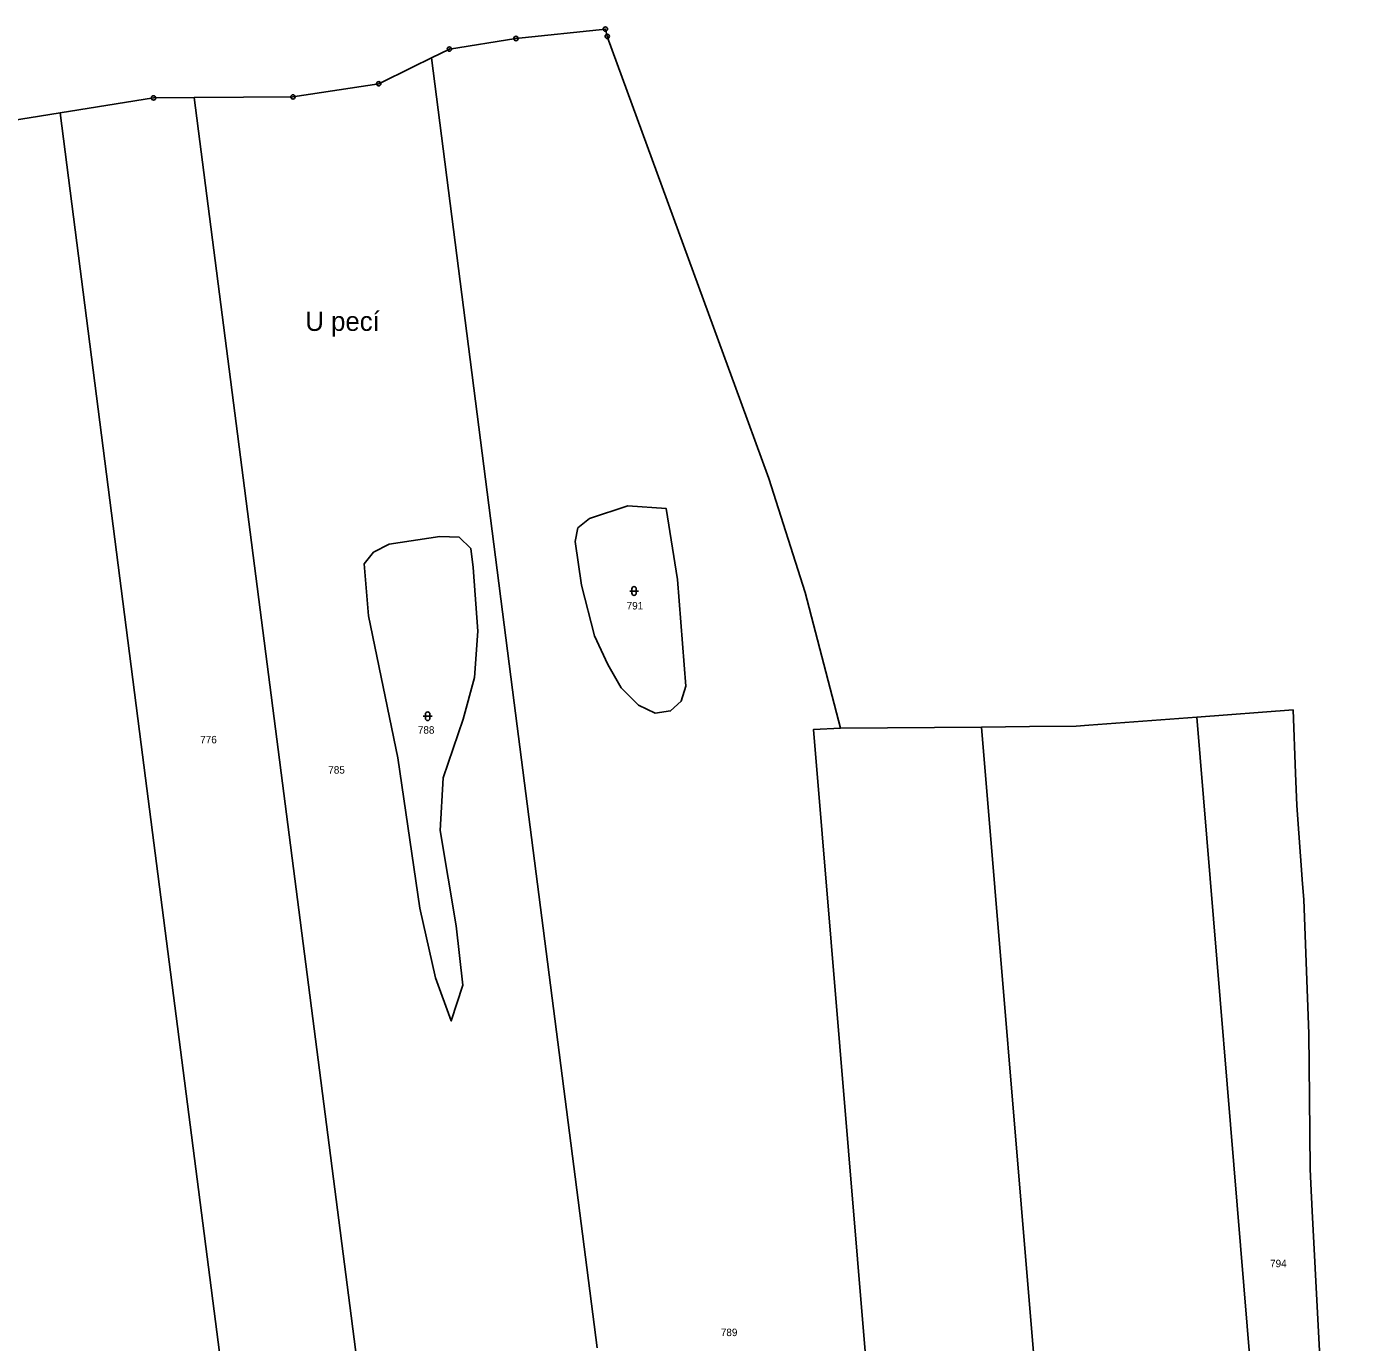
# Model space of a CAD drawing. Extents: x -754445 to -751443, y -1030748 to -1028224.
# Drawn here: x -751875.1 to -751567.6, y -1028889.3 to -1028588.8 of the extents above; entities that cross this region are included whole.
import ezdxf
from ezdxf.enums import TextEntityAlignment as Align

# ---------------------------------------------------------------- set-up
doc = ezdxf.new("R2010")
doc.units = 0
doc.header["$LTSCALE"] = 0.68
for name, color, linetype, lineweight in [('1', 7, 'Continuous', 25), ('3', 7, 'Continuous', 25), ('7', 7, 'Continuous', 13), ('8', 7, 'Continuous', 25)]:
    doc.layers.add(name, color=color, linetype=linetype, lineweight=lineweight)
doc.layers.add('2', color=7, linetype='Continuous')

msp = doc.modelspace()

# ---------------------------------------------------------------- linework, layer by layer
at = {"layer": '1'}
for p, q in [((-751657.05, -1028748.75), (-751689.28, -1028749)), ((-751580.13, -1028885.51), (-751581.5, -1028859.37))]:
    msp.add_line(p, q, dxfattribs=at)
for points in [[(-751742.99, -1028589.3), (-751763.44, -1028591.45), (-751778.63, -1028593.86), (-751782.74, -1028595.88)], [(-751713.49, -1028670.53), (-751714.87, -1028666.76), (-751742.56, -1028590.96), (-751742.99, -1028589.3)], [(-751782.74, -1028595.88), (-751787.07, -1028598), (-751794.77, -1028601.78)], [(-751744.86, -1028890.61), (-751763.8, -1028743.25), (-751782.74, -1028595.88)], [(-751794.77, -1028601.78), (-751814.38, -1028604.79), (-751836.91, -1028604.96)], [(-751836.91, -1028604.96), (-751846.22, -1028605.03), (-751867.56, -1028608.43)], [(-751799.79, -1028893.34), (-751818.35, -1028749.15), (-751836.91, -1028604.96)], [(-751867.56, -1028608.43), (-751881.26, -1028610.61), (-751910.89, -1028616.28), (-751944.04, -1028629.9), (-751979.64, -1028641.44)], [(-751830.47, -1028896.99), (-751849.02, -1028752.71), (-751867.56, -1028608.43)], [(-751697.32, -1028717.98), (-751705.65, -1028691.99), (-751713.49, -1028670.53)], [(-751671.43, -1029039.02), (-751683.44, -1028894.15), (-751695.44, -1028749.28), (-751689.28, -1028749), (-751697.32, -1028717.98)], [(-751583.3, -1029043.19), (-751595.6, -1028894.85), (-751607.89, -1028746.5), (-751632.56, -1028748.35), (-751635.42, -1028748.57), (-751646.07, -1028748.66), (-751657.05, -1028748.75)], [(-751583.7, -1028784.54), (-751585.02, -1028766.67), (-751585.31, -1028759.32), (-751585.88, -1028744.84), (-751607.89, -1028746.5)], [(-751632.9, -1029040.11), (-751644.98, -1028894.43), (-751657.05, -1028748.75)], [(-751582.15, -1028833.42), (-751582.29, -1028818.87), (-751583.44, -1028788.14), (-751583.7, -1028784.54)], [(-751581.5, -1028859.37), (-751581.83, -1028853.05), (-751582, -1028849.75), (-751582.15, -1028833.42)], [(-751567.61, -1028981.3), (-751567.93, -1028978.56), (-751569.19, -1028970.81), (-751571.86, -1028954.03), (-751578.84, -1028910.21), (-751580.13, -1028885.51)]]:
    msp.add_lwpolyline(points, dxfattribs=at)
for points in [[(-751737.87, -1028698.19), (-751729.09, -1028698.85), (-751726.54, -1028715.07), (-751724.65, -1028739.45), (-751725.69, -1028742.86), (-751728.11, -1028745.07), (-751731.63, -1028745.55), (-751735.39, -1028743.76), (-751739.41, -1028739.83), (-751742.43, -1028734.48), (-751745.46, -1028727.93), (-751748.45, -1028716.35), (-751749.89, -1028706.38), (-751749.29, -1028703.25), (-751746.62, -1028701.09)], [(-751780.81, -1028705.19), (-751776.43, -1028705.37), (-751773.74, -1028707.95), (-751773.22, -1028712.3), (-751772.11, -1028726.84), (-751772.9, -1028737.45), (-751775.45, -1028746.97), (-751780.03, -1028760.33), (-751780.7, -1028772.4), (-751777.06, -1028794.17), (-751775.57, -1028807.75), (-751778.2, -1028815.9), (-751781.83, -1028806.03), (-751785.42, -1028790.17), (-751790.43, -1028755.81), (-751797.08, -1028723.31), (-751798.13, -1028711.48), (-751795.96, -1028708.83), (-751792.36, -1028707.01)]]:
    msp.add_lwpolyline(points, close=True, dxfattribs=at)
at = {"layer": '3'}
for p, q in [((-751737.441, -1028717.681), (-751735.439, -1028717.681)), ((-751736.941, -1028717.181), (-751736.941, -1028718.182)), ((-751735.939, -1028718.182), (-751735.939, -1028717.181)), ((-751784.591, -1028746.281), (-751782.589, -1028746.281)), ((-751784.091, -1028745.781), (-751784.091, -1028746.782)), ((-751783.089, -1028746.782), (-751783.089, -1028745.781))]:
    msp.add_line(p, q, dxfattribs=at)
for centre, start, end in [((-751736.44, -1028717.1809), 0, 180), ((-751736.44, -1028718.1809), 180, 359.98789), ((-751783.59, -1028745.7809), 0, 180), ((-751783.59, -1028746.7809), 180, 359.98789)]:
    msp.add_arc(centre, 0.5, start, end, dxfattribs=at)
at = {"layer": '8'}
for centre, radius in [((-751742.99, -1028589.2999), 0.5), ((-751742.56, -1028590.9599), 0.5), ((-751742.99, -1028589.2999), 0.0303), ((-751778.63, -1028593.8599), 0.5), ((-751778.63, -1028593.8599), 0.0303), ((-751763.44, -1028591.4499), 0.5), ((-751763.44, -1028591.4499), 0.0303), ((-751742.56, -1028590.9599), 0.0303), ((-751794.77, -1028601.7799), 0.5), ((-751794.77, -1028601.7799), 0.0303), ((-751846.22, -1028605.0299), 0.5), ((-751846.22, -1028605.0299), 0.0303), ((-751814.38, -1028604.7899), 0.5), ((-751814.38, -1028604.7899), 0.0303)]:
    msp.add_circle(centre, radius, dxfattribs=at)

# ---------------------------------------------------------------- texts
at = {"layer": '2'}
for s, p in [('791', (-751736.239, -1028721.886)), ('788', (-751783.939, -1028750.266)), ('776', (-751833.659, -1028752.476)), ('785', (-751804.409, -1028759.396)), ('794', (-751589.249, -1028872.166)), ('789', (-751714.729, -1028887.906))]:
    msp.add_text(s, height=1.7, dxfattribs=at).set_placement(p, align=Align.CENTER)
at = {"layer": '7'}
msp.add_text('U pecí', height=4.4, dxfattribs=at).set_placement((-751803.039, -1028658.25), align=Align.CENTER)

doc.saveas('drawing.dxf')
